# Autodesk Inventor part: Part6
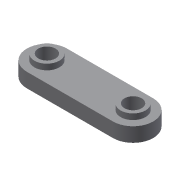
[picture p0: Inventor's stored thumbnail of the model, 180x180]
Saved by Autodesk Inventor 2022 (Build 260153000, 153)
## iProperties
Created: 2002-01
Part Number: Part6
Document SubType Name: Modeling
Designer: ***
Density: 1 g/cm^3
Mass: 21.6911 g
Surface Area: 77.1136 cm^2
Volume: 21.6911 cm^3
Material: Generic
Appearance: Default
Control State: 0
Master: False
Checked Out: False
Shininess: 77.0
Length Units: 11269
Angle Units: 11279
Time Units: 11290
Mass Units: 11283
Length Display Precision: 3
Angle Display Precision: 2
Density: 0.0
Volumn: 0.0
Area: 0.0
PropertySet Name: Model Information
Author: ***
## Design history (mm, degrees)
sketch "Sketch1"
  geometry: L1 (-33.118, 12.346)-(26.882, 12.361); L2 (-33.111, -15.654)-(26.889, -15.639); C1 r 6 at (-33.114, -1.654); C2 r 6 at (26.886, -1.639); A1 r 14 centre (-33.114, -1.654) between (-33.118, 12.346) and (-33.111, -15.654); A2 r 14 centre (26.886, -1.639) between (26.889, -15.639) and (26.882, 12.361)
  constraints: 4 centre point, 4 end point, 4 point on circle, 4 tangent, 2 coincident, 2 equal radius
  dimensions: "d0" = 60 distance of L1.start L1.end; "d1" = 14 radius of A1; "d2" = 12 diameter of C1
extrude "Extrusion1" new body sketch "Sketch1" distance "d3" = 10; taper "d4" = 0 deg
sketch "Sketch2"
  geometry: C1 r 6 at (26.886, -1.639) reference; C2 r 6 at (-33.114, -1.654) reference; C3 r 8.694 at (-33.114, -1.654); C4 r 8.694 at (26.886, -1.639)
  constraints: 2 centre point, 2 coincident, 1 equal radius
extrude "Extrusion2" join sketch "Sketch2" distance "d5" = 4; taper "d6" = 0 deg
body "Solid1"
